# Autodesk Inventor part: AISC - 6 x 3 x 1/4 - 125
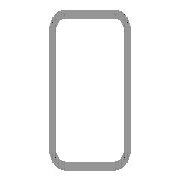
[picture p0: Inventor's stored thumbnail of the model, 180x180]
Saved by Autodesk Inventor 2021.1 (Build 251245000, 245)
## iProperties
Created: 2018-01
Part Number: AISC - 6 x 3 x 1/4 - 125
Material: Steel, Galvanized
Description: Tube
Document SubType Name: Modeling
Standard: AISC
Designer: u1426
Standards Organization: ANSI
Language: en-US
Size Designation: 6 x 3 x 1/4 - 125
Categories: <MemberInstance><Categories><Category DisplayName="Structural Shapes" InternalName="089c4875-fa83-4c05-b084-43b9cc11f5ed" Mnemonic="GRDR"><CategoryParameter Dis
Stock Number: 6 x 3 x 1/4
Density: 7.85 g/cm^3
Appearance: Galvanized
IsCustomPart: 1
G_L: 125.000 in
Author: u1426
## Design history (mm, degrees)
node "Start plane"
sketch "Sketch"
  geometry: L1 (-38.1, -63.5)-(-38.1, 63.5); L2 (-25.4, 76.2)-(25.4, 76.2); L3 (38.1, 63.5)-(38.1, -63.5); L4 (25.4, -76.2)-(-25.4, -76.2); L5 (-25.4, 69.85)-(25.4, 69.85); L6 (31.75, 63.5)-(31.75, -63.5); L7 (25.4, -69.85)-(-25.4, -69.85); L8 (-31.75, -63.5)-(-31.75, 63.5); L9 (0, 110.362)-(0, -110.362) reference; L10 (-57.022, 0)-(57.022, 0) reference; A1 r 12.7 centre (-25.4, -63.5) between (-38.1, -63.5) and (-25.4, -76.2); A2 r 12.7 centre (-25.4, 63.5) between (-25.4, 76.2) and (-38.1, 63.5); A3 r 12.7 centre (25.4, 63.5) between (38.1, 63.5) and (25.4, 76.2); A4 r 12.7 centre (25.4, -63.5) between (25.4, -76.2) and (38.1, -63.5); A5 r 6.35 centre (-25.4, 63.5) between (-25.4, 69.85) and (-31.75, 63.5); A6 r 6.35 centre (25.4, 63.5) between (31.75, 63.5) and (25.4, 69.85); A7 r 6.35 centre (25.4, -63.5) between (25.4, -69.85) and (31.75, -63.5); A8 r 6.35 centre (-25.4, -63.5) between (-31.75, -63.5) and (-25.4, -69.85)
  constraints: 16 end point, 16 point on circle, 8 centre point, 8 tangent, 4 parallel, 3 equal radius, 2 perpendicular, 7 other
  dimensions: "d10" = 152.4 distance between parallel lines of L2 L4 (= G_H); "d11" = 76.2 distance between parallel lines of L1 L3 (= G_W); "d12" = 6.35 distance between parallel lines of L3 L6 (= G_T); "d15" = 76.2 distance between parallel lines of L2 L10 (= 0.5 x d10); "d16" = 38.1 distance between parallel lines of L9 L3 (= 0.5 x d11); "d17" = 12.7 radius of A1 (= G_IR)
extrude "Extrusion2" new body sketch "Sketch" distance "d20" = 495.3; taper "d21" = 0 deg; dims "d22" = 457.2, "d23" = 0
sketch "Sketch5"
  geometry: L1 (12.7, -495.3)-(12.7, -200.025); L2 (0, 0)-(-12.7, 0) reference; L3 (12.7, -200.025)-(-12.7, 0); L4 (-12.7, -495.3)-(0, -495.3) reference; L5 (-12.7, -495.3)-(12.7, -495.3); L6 (0, -495.3)-(50.8, -495.3) reference; L7 (-12.7, 0)-(-12.7, -495.3) reference; L8 (-12.7, -495.3)-(-12.7, 0); 2 further points
  constraints: 8 end point, 1 collinear, 1 vertical
  dimensions: "d25" = 295.275 distance of L1.start L1.end
extrude "Extrusion3" cut sketch "Sketch5" extent not by distance; stored distance "d26" = 0; taper "d27" = 0 deg
sketch "Sketch6"
  geometry: L1 (12.7, -495.3)-(12.7, -200.025) reference; L2 (0, 0)-(-12.7, 0) reference; L3 (12.7, -200.025)-(-12.7, 0); L4 (-6.299, 0)-(19.05, -199.623); L5 (19.05, -199.623)-(19.05, -495.3); L6 (12.7, -200.025)-(0, -100.013) reference; L7 (12.7, -200.025)-(12.7, -495.3); L8 (12.7, -495.3)-(19.05, -495.3); L9 (-12.7, 0)-(-6.299, 0); L10 (50.8, 0)-(0, 0) reference; 2 further points
  constraints: 12 end point, 1 perpendicular
  dimensions: "d28" = 6.35 distance between parallel lines of L3 L4
extrude "Extrusion4" join sketch "Sketch6" distance "d29" = 139.7; taper "d30" = 0 deg
body "Solid2"
other parameters: "G_W" = 76.2 [user parameter; used in 1 equation term], "G_H" = 152.4 [user parameter; used in 1 equation term], "G_T" = 6.35 [user parameter; used in 1 equation term], "G_IR" = 12.7 [user parameter; used in 1 equation term], "G_L" = 3175 (= d19) [user parameter], "G_OFFSET_START" = 0 [user parameter; used in 1 equation term], "G_OFFSET_END" = 0 [user parameter], "d13" = 0 (computed from G_OFFSET_START), "B_L" = 3175 [user parameter], "d19" = 3175 (derived)
